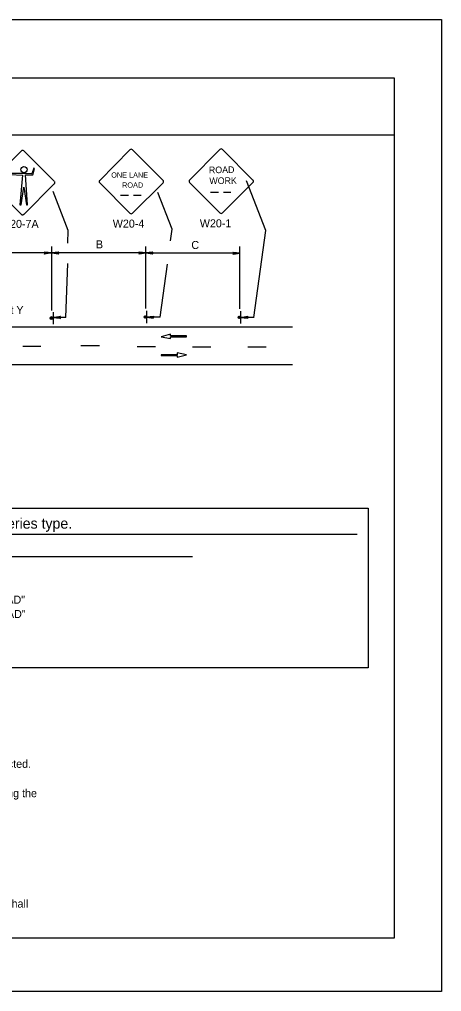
# Model space of a CAD drawing. Extents: x -14145 to -13521, y 30244 to 30661.
# Drawn here: x -13870.25 to -13859.17, y 30451.81 to 30477.31 of the extents above; entities that cross this region are included whole.
import ezdxf

# ---------------------------------------------------------------- set-up
doc = ezdxf.new("R2010")
doc.units = 0
for name, color, linetype in [('1', 7, 'Continuous'), ('10', 7, 'Continuous'), ('2', 7, 'Continuous'), ('61', 7, 'Continuous')]:
    doc.layers.add(name, color=color, linetype=linetype)

msp = doc.modelspace()

# ---------------------------------------------------------------- linework, layer by layer
at = {"layer": '1'}
for p, q in [((-13870.202, 30473.858), (-13870.997, 30473.063)), ((-13869.34, 30473.063), (-13870.135, 30473.858)), ((-13867.353, 30473.887), (-13868.148, 30473.084)), ((-13866.484, 30473.084), (-13867.286, 30473.887)), ((-13864.993, 30473.896), (-13865.788, 30473.093)), ((-13864.124, 30473.093), (-13864.926, 30473.896)), ((-13870.082, 30473.266), (-13870.705, 30473.266)), ((-13869.932, 30473.258), (-13870.082, 30473.266)), ((-13869.88, 30473.408), (-13869.932, 30473.258)), ((-13869.902, 30473.228), (-13869.857, 30473.401)), ((-13869.857, 30473.401), (-13869.88, 30473.408)), ((-13870.502, 30473.243), (-13870.172, 30473.221)), ((-13870.172, 30473.221), (-13870.24, 30472.441)), ((-13870.045, 30472.441), (-13870.097, 30473.228)), ((-13870.097, 30473.228), (-13869.902, 30473.228)), ((-13868.148, 30473.018), (-13867.353, 30472.223)), ((-13867.286, 30472.223), (-13866.484, 30473.018)), ((-13865.788, 30473.027), (-13864.993, 30472.232)), ((-13864.926, 30472.232), (-13864.124, 30473.027)), ((-13863.783, 30471.772), (-13864.295, 30473.076)), ((-13870.997, 30472.996), (-13870.202, 30472.193)), ((-13870.21, 30472.441), (-13870.142, 30472.906)), ((-13870.142, 30472.906), (-13870.067, 30472.441)), ((-13870.135, 30472.193), (-13869.34, 30472.996)), ((-13868.973, 30471.774), (-13869.372, 30472.792)), ((-13866.246, 30471.808), (-13866.62, 30472.763)), ((-13865.24, 30472.779), (-13865.029, 30472.779)), ((-13864.897, 30472.779), (-13864.703, 30472.779)), ((-13867.6, 30472.694), (-13867.389, 30472.694)), ((-13867.257, 30472.694), (-13867.063, 30472.694)), ((-13870.24, 30472.441), (-13870.21, 30472.441)), ((-13870.067, 30472.441), (-13870.045, 30472.441)), ((-13868.983, 30471.441), (-13868.973, 30471.774)), ((-13866.288, 30471.501), (-13866.246, 30471.808)), ((-13864.098, 30469.491), (-13863.783, 30471.772)), ((-13869.407, 30469.671), (-13869.407, 30471.347)), ((-13866.935, 30469.725), (-13866.935, 30471.347)), ((-13864.469, 30469.719), (-13864.469, 30471.347)), ((-13869.407, 30471.182), (-13874.291, 30471.182)), ((-13866.935, 30471.182), (-13869.407, 30471.182)), ((-13864.469, 30471.176), (-13866.935, 30471.176)), ((-13869.036, 30469.491), (-13868.981, 30470.903)), ((-13866.564, 30469.497), (-13866.372, 30470.887)), ((-13869.365, 30469.629), (-13869.365, 30469.311)), ((-13869.035, 30469.491), (-13869.365, 30469.491)), ((-13866.917, 30469.659), (-13866.917, 30469.341)), ((-13866.563, 30469.497), (-13866.917, 30469.497)), ((-13864.451, 30469.653), (-13864.451, 30469.335)), ((-13864.097, 30469.491), (-13864.451, 30469.491)), ((-13889.363, 30469.241), (-13863.083, 30469.241)), ((-13866.289, 30469.049), (-13866.531, 30468.983)), ((-13866.531, 30468.983), (-13866.287, 30468.937)), ((-13866.289, 30469.004), (-13866.289, 30469.049)), ((-13865.873, 30469.004), (-13866.289, 30469.004)), ((-13866.287, 30468.937), (-13866.287, 30468.982)), ((-13866.287, 30468.982), (-13865.873, 30468.982)), ((-13865.873, 30468.982), (-13865.873, 30469.004)), ((-13869.689, 30468.725), (-13870.169, 30468.725)), ((-13868.155, 30468.743), (-13868.641, 30468.743)), ((-13866.679, 30468.719), (-13867.165, 30468.719)), ((-13865.227, 30468.713), (-13865.713, 30468.713)), ((-13863.775, 30468.707), (-13864.261, 30468.707)), ((-13866.117, 30468.513), (-13866.531, 30468.513)), ((-13866.531, 30468.513), (-13866.531, 30468.491)), ((-13866.531, 30468.491), (-13866.114, 30468.491)), ((-13865.873, 30468.512), (-13866.117, 30468.559)), ((-13866.117, 30468.559), (-13866.117, 30468.513)), ((-13866.114, 30468.446), (-13865.873, 30468.512)), ((-13866.114, 30468.491), (-13866.114, 30468.446)), ((-13889.363, 30468.257), (-13863.083, 30468.257))]:
    msp.add_line(p, q, dxfattribs=at)
for points in [[(-13869.587, 30471.206), (-13869.581, 30471.194), (-13869.407, 30471.182), (-13869.587, 30471.206), (-13869.599, 30471.212), (-13869.407, 30471.182), (-13869.581, 30471.176), (-13869.587, 30471.164), (-13869.407, 30471.182), (-13869.599, 30471.152), (-13869.587, 30471.164)], [(-13869.233, 30471.158), (-13869.239, 30471.17), (-13869.407, 30471.182), (-13869.233, 30471.158), (-13869.221, 30471.152), (-13869.407, 30471.182), (-13869.239, 30471.188), (-13869.233, 30471.2), (-13869.407, 30471.182), (-13869.221, 30471.212), (-13869.233, 30471.2)], [(-13867.109, 30471.2), (-13867.103, 30471.188), (-13866.935, 30471.182), (-13867.109, 30471.2), (-13867.121, 30471.212), (-13866.935, 30471.182), (-13867.103, 30471.17), (-13867.109, 30471.158), (-13866.935, 30471.182), (-13867.121, 30471.152), (-13867.109, 30471.158)], [(-13866.761, 30471.158), (-13866.767, 30471.17), (-13866.935, 30471.182), (-13866.761, 30471.158), (-13866.749, 30471.152), (-13866.935, 30471.182), (-13866.767, 30471.188), (-13866.761, 30471.2), (-13866.935, 30471.182), (-13866.749, 30471.212), (-13866.761, 30471.2)], [(-13864.643, 30471.194), (-13864.637, 30471.182), (-13864.469, 30471.176), (-13864.643, 30471.194), (-13864.655, 30471.206), (-13864.469, 30471.176), (-13864.637, 30471.164), (-13864.643, 30471.152), (-13864.469, 30471.176), (-13864.655, 30471.146), (-13864.643, 30471.152)], [(-13869.191, 30469.467), (-13869.197, 30469.479), (-13869.365, 30469.491), (-13869.191, 30469.467), (-13869.179, 30469.461), (-13869.365, 30469.491), (-13869.197, 30469.497), (-13869.191, 30469.509), (-13869.365, 30469.491), (-13869.179, 30469.521), (-13869.191, 30469.509)], [(-13866.737, 30469.473), (-13866.743, 30469.485), (-13866.917, 30469.497), (-13866.737, 30469.473), (-13866.731, 30469.467), (-13866.917, 30469.497), (-13866.743, 30469.503), (-13866.737, 30469.515), (-13866.917, 30469.497), (-13866.731, 30469.527), (-13866.737, 30469.515)], [(-13864.271, 30469.467), (-13864.277, 30469.479), (-13864.451, 30469.491), (-13864.271, 30469.467), (-13864.265, 30469.461), (-13864.451, 30469.491), (-13864.277, 30469.497), (-13864.271, 30469.509), (-13864.451, 30469.491), (-13864.265, 30469.521), (-13864.271, 30469.509)]]:
    msp.add_lwpolyline(points, dxfattribs=at)
for centre, radius in [((-13870.135, 30473.366), 0.0844), ((-13869.415, 30469.471), 0.0325), ((-13866.953, 30469.501), 0.0298), ((-13864.487, 30469.495), 0.0298)]:
    msp.add_circle(centre, radius, dxfattribs=at)
for centre, radius, start, end in [((-13870.17, 30473.826), 0.0465, 45, 135), ((-13867.32, 30473.855), 0.0465, 45, 135), ((-13864.96, 30473.864), 0.0465, 45, 135), ((-13869.371, 30473.027), 0.0465, 315, 45), ((-13868.115, 30473.052), 0.0465, 135, 225), ((-13866.517, 30473.052), 0.0465, 315, 45), ((-13865.755, 30473.061), 0.0465, 135, 225), ((-13864.157, 30473.061), 0.0465, 315, 45), ((-13870.17, 30472.228), 0.0465, 225, 315), ((-13867.32, 30472.257), 0.0465, 225, 315), ((-13864.96, 30472.266), 0.0465, 225, 315), ((-13869.415, 30469.482), 0.0214, 355.7499, 350.479), ((-13866.952, 30469.502), 0.0214, 355.7499, 350.479), ((-13864.486, 30469.496), 0.0214, 355.7499, 350.479)]:
    msp.add_arc(centre, radius, start, end, dxfattribs=at)
at = {"layer": '10'}
for p, q in [((-13891.874, 30475.777), (-13860.422, 30475.777)), ((-13860.422, 30475.777), (-13860.422, 30453.207)), ((-13891.874, 30474.277), (-13860.422, 30474.277)), ((-13860.422, 30453.207), (-13891.874, 30453.207))]:
    msp.add_line(p, q, dxfattribs=at)
at = {"layer": '2'}
for p, q in [((-13881.338, 30463.805), (-13861.388, 30463.805)), ((-13877.152, 30463.221), (-13865.715, 30463.221))]:
    msp.add_line(p, q, dxfattribs=at)
msp.add_lwpolyline([(-13881.564, 30464.483), (-13861.099, 30464.483), (-13861.099, 30460.296), (-13881.564, 30460.296)], close=True, dxfattribs=at)
at = {"layer": '61'}
msp.add_lwpolyline([(-13892.174, 30477.307), (-13859.174, 30477.307), (-13859.174, 30451.807), (-13892.174, 30451.807)], close=True, dxfattribs=at)

# ---------------------------------------------------------------- texts
at = {"layer": '1'}
for s, height, p in [('ONE LANE', 0.1386, (-13867.845, 30473.156)), ('ROAD', 0.1389, (-13867.56, 30472.893)), ('      B = 500 ft., W20-4 sign distance plaque to read 1000 ft. or "AHEAD"', 0.21, (-13879.025, 30461.982)), ('      C = 500 ft., W20-1 sign distance plaque to read 1500 ft. or "AHEAD"', 0.21, (-13879.025, 30461.605))]:
    msp.add_text(s, height=height, dxfattribs=at).set_placement(p)
for s, height, rotation, p in [('ROAD', 0.1735, 0.7566, (-13865.28, 30473.271)), ('WORK', 0.1733, 0.7588, (-13865.268, 30472.986))]:
    msp.add_text(s, height=height, rotation=rotation, dxfattribs=at).set_placement(p)
at = {"layer": '2'}
for s, height, p in [('W20-7A', 0.21, (-13870.765, 30471.839)), ('W20-4', 0.21, (-13867.804, 30471.846)), ('W20-1', 0.21, (-13865.519, 30471.854)), ('B', 0.21, (-13868.246, 30471.303)), ('C', 0.21, (-13865.742, 30471.285)), ('Point Y', 0.21, (-13871.053, 30469.58)), ('Distance plaques on Advance Warning signs shall be the same series type.', 0.2772, (-13881.233, 30463.949)), ('    b. Sight distance between the flagger and any vehicle between Points X and Y will be unobstructed.', 0.21, (-13882.626, 30457.676)), ('    d. The ADT is not greater than approximately 1500, or the average 5-minute traffic volume during the', 0.21, (-13882.626, 30456.905)), ('    resulting from the lane closure might extend through a highway-rail grade crossing, provisions shall ', 0.21, (-13882.62, 30454.009))]:
    msp.add_text(s, height=height, dxfattribs=at).set_placement(p)

doc.saveas('drawing.dxf')
